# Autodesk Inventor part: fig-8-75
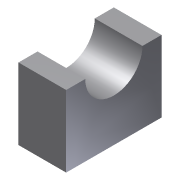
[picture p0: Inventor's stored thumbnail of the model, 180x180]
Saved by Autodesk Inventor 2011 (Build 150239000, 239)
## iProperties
Shininess: 77.0
Length Units: 11269
Angle Units: 11279
Time Units: 11290
Mass Units: 11283
Length Display Precision: 3
Angle Display Precision: 2
Created: 2002-01
Part Number: fig-8-75
Document SubType Name: Modeling
Designer: ***
Density: 1 g/cm^3
Density: 0.0
Volumn: 0.0
Area: 0.0
PropertySet Name: Model Information
Control State: 0
Master: False
Checked Out: False
Author: ***
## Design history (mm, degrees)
sketch "Sketch5"
  geometry: L1 (-22.226, 10.275)-(-14.226, 10.275); L2 (9.774, 10.275)-(17.774, 10.275); L3 (17.774, 10.275)-(17.774, -19.725); L4 (17.774, -19.725)-(-22.226, -19.725); L5 (-22.226, -19.725)-(-22.226, 10.275); A1 r 12 centre (-2.226, 10.275) between (-14.226, 10.275) and (9.774, 10.275)
  constraints: 10 end point, 2 equal length, 2 parallel, 2 point on circle, 1 centre point, 1 collinear, 1 horizontal, 1 perpendicular, 1 point on line
  dimensions: "d7" = 40 distance of L3.end L4.end; "d8" = 30 distance of L2.end L3.end; "d9" = 12 radius of A1
extrude "Extrusion2" new body sketch "Sketch5" distance "d10" = 20; taper "d11" = 0 deg
workplane "Work Plane3"
sketch "Sketch6"
  geometry: L1 (19.321, -18.091)-(12.314, -18.091); L2 (12.314, -18.091)-(12.314, -11.217); L3 (12.314, -11.217)-(7.026, -11.217); L4 (7.026, -11.217)-(7.026, 7.425); L5 (7.026, 7.425)-(7.026, 14.035); L6 (7.026, 14.035)-(-10.029, 14.035)
  constraints: 12 end point, 4 parallel, 1 horizontal, 1 perpendicular
split "Split5" sketch "Sketch6"
body "Solid1"
other parameters: "d12" = 15
